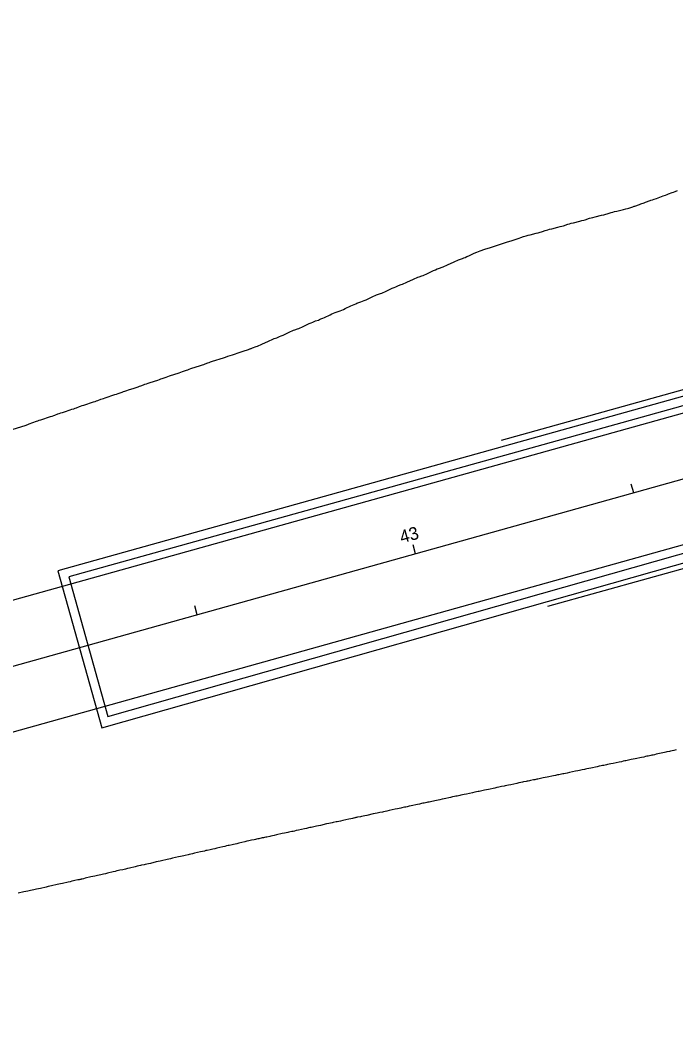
# Model space of a CAD drawing. Extents: x 1512289 to 1544686, y 552531 to 589211.
# Drawn here: x 1542830.9 to 1542975.5, y 587195.3 to 587418.5 of the extents above; entities that cross this region are included whole.
import ezdxf

# ---------------------------------------------------------------- set-up
doc = ezdxf.new("R2010")
doc.units = 0
for name, color, linetype in [('DR_X_Flood_Boundary', 7, 'Continuous'), ('DR_X_Underdrain', 7, 'Continuous'), ('DT_P_Graded_Shoulder', 7, 'Continuous'), ('GE_X_CL_20', 7, 'Continuous'), ('GK_Visualization', 7, 'Continuous'), ('PV_P_Text', 7, 'Continuous'), ('RW_P_Const_Limits', 7, 'Continuous')]:
    doc.layers.add(name, color=color, linetype=linetype)

msp = doc.modelspace()

# ---------------------------------------------------------------- linework, layer by layer
at = {"layer": 'DR_X_Flood_Boundary'}
for points in [[(1542829.08, 587328.21), (1542832.15, 587329.2), (1542832.7, 587329.38), (1542832.84, 587329.43), (1542834.45, 587330.03), (1542834.72, 587330.13), (1542835.05, 587330.24), (1542835.43, 587330.37), (1542835.87, 587330.52), (1542837.1, 587330.91), (1542837.53, 587331.06), (1542837.91, 587331.18), (1542838.24, 587331.3), (1542838.51, 587331.4), (1542839.17, 587331.64), (1542839.45, 587331.74), (1542839.78, 587331.86), (1542840.16, 587331.99), (1542840.59, 587332.13), (1542841.83, 587332.53), (1542842.26, 587332.67), (1542842.64, 587332.8), (1542842.97, 587332.91), (1542843.24, 587333.01), (1542843.9, 587333.26), (1542844.17, 587333.35), (1542844.5, 587333.47), (1542844.88, 587333.6), (1542845.32, 587333.74), (1542846.56, 587334.14), (1542846.99, 587334.28), (1542847.37, 587334.41), (1542847.7, 587334.53), (1542847.97, 587334.62), (1542848.63, 587334.87), (1542848.9, 587334.97), (1542849.23, 587335.08), (1542849.61, 587335.21), (1542850.05, 587335.35), (1542851.29, 587335.75), (1542851.72, 587335.9), (1542852.11, 587336.02), (1542852.43, 587336.14), (1542852.7, 587336.24), (1542853.35, 587336.48), (1542853.63, 587336.58), (1542853.95, 587336.69), (1542854.34, 587336.82), (1542854.77, 587336.96), (1542856.02, 587337.36), (1542856.45, 587337.51), (1542856.84, 587337.64), (1542857.16, 587337.75), (1542857.43, 587337.85), (1542858.08, 587338.09), (1542858.35, 587338.19), (1542858.68, 587338.3), (1542859.06, 587338.43), (1542859.5, 587338.57), (1542861.19, 587339.12), (1542861.57, 587339.25), (1542861.9, 587339.36), (1542862.16, 587339.46), (1542862.81, 587339.7), (1542863.08, 587339.79), (1542863.41, 587339.91), (1542863.79, 587340.04), (1542865.92, 587340.73), (1542866.3, 587340.86), (1542866.63, 587340.97), (1542866.9, 587341.07), (1542867.54, 587341.31), (1542867.81, 587341.4), (1542868.13, 587341.52), (1542868.52, 587341.64), (1542870.65, 587342.34), (1542871.03, 587342.47), (1542871.36, 587342.58), (1542871.63, 587342.68), (1542872.26, 587342.91), (1542872.53, 587343.01), (1542872.86, 587343.12), (1542873.24, 587343.25), (1542875.71, 587344.05), (1542876.13, 587344.19), (1542876.63, 587344.36), (1542877.65, 587344.7), (1542879.35, 587345.25), (1542880.06, 587345.48), (1542881.18, 587345.87), (1542881.35, 587345.93), (1542881.48, 587345.97), (1542881.56, 587346.01), (1542881.71, 587346.08), (1542881.79, 587346.11), (1542881.91, 587346.16), (1542882.08, 587346.22), (1542882.92, 587346.51), (1542883.18, 587346.6), (1542883.5, 587346.73), (1542883.87, 587346.9), (1542884.29, 587347.09), (1542885.49, 587347.66), (1542885.91, 587347.86), (1542886.28, 587348.02), (1542886.6, 587348.15), (1542886.86, 587348.25), (1542887.49, 587348.46), (1542887.75, 587348.56), (1542888.06, 587348.69), (1542888.43, 587348.85), (1542888.86, 587349.05), (1542890.06, 587349.61), (1542890.48, 587349.81), (1542890.85, 587349.97), (1542891.17, 587350.1), (1542891.43, 587350.2), (1542892.05, 587350.41), (1542892.32, 587350.51), (1542892.63, 587350.64), (1542893, 587350.8), (1542893.42, 587351), (1542894.62, 587351.56), (1542895.05, 587351.76), (1542895.42, 587351.92), (1542895.73, 587352.05), (1542896, 587352.15), (1542896.62, 587352.36), (1542896.88, 587352.46), (1542897.2, 587352.59), (1542897.57, 587352.75), (1542897.99, 587352.95), (1542899.19, 587353.51), (1542899.62, 587353.71), (1542899.98, 587353.87), (1542900.3, 587354), (1542900.56, 587354.1), (1542901.19, 587354.32), (1542901.45, 587354.41), (1542901.77, 587354.54), (1542902.14, 587354.71), (1542902.56, 587354.9), (1542903.76, 587355.47), (1542904.18, 587355.66), (1542904.55, 587355.82), (1542904.87, 587355.95), (1542905.13, 587356.05), (1542905.76, 587356.27), (1542906.02, 587356.37), (1542906.34, 587356.5), (1542906.71, 587356.66), (1542907.13, 587356.85), (1542908.33, 587357.42), (1542908.75, 587357.61), (1542909.12, 587357.77), (1542909.44, 587357.9), (1542909.7, 587358), (1542910.33, 587358.22), (1542910.59, 587358.32), (1542910.9, 587358.45), (1542911.27, 587358.61), (1542911.7, 587358.8), (1542912.9, 587359.37), (1542913.32, 587359.56), (1542913.69, 587359.72), (1542914, 587359.85), (1542914.27, 587359.95), (1542914.89, 587360.17), (1542915.16, 587360.27), (1542915.47, 587360.4), (1542915.84, 587360.56), (1542916.26, 587360.76), (1542917.46, 587361.32), (1542917.89, 587361.51), (1542918.26, 587361.67), (1542918.57, 587361.8), (1542918.83, 587361.9), (1542919.46, 587362.12), (1542919.73, 587362.22), (1542920.04, 587362.35), (1542920.41, 587362.51), (1542920.83, 587362.71), (1542922.03, 587363.27), (1542922.45, 587363.46), (1542922.81, 587363.62), (1542923.11, 587363.74), (1542923.35, 587363.83), (1542923.91, 587364.03), (1542924.15, 587364.12), (1542924.45, 587364.24), (1542924.81, 587364.4), (1542925.22, 587364.59), (1542926.42, 587365.15), (1542926.84, 587365.35), (1542927.21, 587365.51), (1542927.53, 587365.64), (1542927.79, 587365.74), (1542928.43, 587365.96), (1542928.69, 587366.06), (1542929.01, 587366.19), (1542929.38, 587366.35), (1542929.8, 587366.54), (1542930.99, 587367.1), (1542931.55, 587367.34), (1542932.34, 587367.63), (1542933.34, 587367.98), (1542934.57, 587368.38), (1542938.15, 587369.54), (1542939.35, 587369.93), (1542940.28, 587370.23), (1542940.92, 587370.44), (1542941.29, 587370.56), (1542941.89, 587370.77), (1542942.15, 587370.86), (1542942.48, 587370.95), (1542942.87, 587371.06), (1542943.34, 587371.18), (1542944.67, 587371.51), (1542945.13, 587371.63), (1542945.53, 587371.73), (1542945.85, 587371.83), (1542946.1, 587371.91), (1542946.67, 587372.11), (1542946.92, 587372.19), (1542947.24, 587372.28), (1542947.64, 587372.39), (1542948.12, 587372.51), (1542949.48, 587372.85), (1542949.95, 587372.97), (1542950.35, 587373.07), (1542950.67, 587373.16), (1542950.91, 587373.24), (1542951.45, 587373.43), (1542951.69, 587373.51), (1542952.01, 587373.6), (1542952.42, 587373.7), (1542952.9, 587373.83), (1542954.3, 587374.17), (1542954.78, 587374.29), (1542955.18, 587374.39), (1542955.49, 587374.48), (1542955.72, 587374.56), (1542956.23, 587374.73), (1542956.46, 587374.81), (1542956.78, 587374.9), (1542957.19, 587375), (1542957.68, 587375.12), (1542959.11, 587375.47), (1542959.61, 587375.59), (1542960.01, 587375.7), (1542960.32, 587375.78), (1542960.54, 587375.85), (1542961.01, 587376.02), (1542961.23, 587376.09), (1542961.55, 587376.18), (1542961.96, 587376.28), (1542962.46, 587376.4), (1542963.93, 587376.76), (1542964.43, 587376.88), (1542964.84, 587376.98), (1542965.15, 587377.07), (1542965.36, 587377.13), (1542965.79, 587377.28), (1542965.96, 587377.34), (1542966.12, 587377.4), (1542966.28, 587377.45), (1542966.44, 587377.51), (1542966.87, 587377.66), (1542967.05, 587377.72), (1542967.25, 587377.79), (1542967.49, 587377.88), (1542967.75, 587377.97), (1542968.5, 587378.24), (1542968.76, 587378.34), (1542969, 587378.42), (1542969.2, 587378.49), (1542969.37, 587378.55), (1542969.79, 587378.7), (1542970, 587378.77), (1542970.3, 587378.88), (1542970.71, 587379.02), (1542971.21, 587379.2), (1542972.68, 587379.73), (1542973.18, 587379.91), (1542973.58, 587380.06), (1542973.87, 587380.17), (1542974.07, 587380.25), (1542974.45, 587380.41), (1542974.64, 587380.48), (1542974.94, 587380.59), (1542975.34, 587380.74), (1542975.85, 587380.92)], [(1542975.54, 587257.52), (1542975.06, 587257.41), (1542974.65, 587257.32), (1542974.33, 587257.24), (1542974.07, 587257.19), (1542973.51, 587257.07), (1542973.27, 587257.02), (1542972.98, 587256.96), (1542972.65, 587256.89), (1542972.27, 587256.8), (1542971.18, 587256.55), (1542970.8, 587256.46), (1542970.47, 587256.39), (1542970.18, 587256.32), (1542969.94, 587256.27), (1542969.37, 587256.16), (1542969.12, 587256.1), (1542968.79, 587256.04), (1542968.39, 587255.95), (1542967.9, 587255.85), (1542966.52, 587255.56), (1542966.04, 587255.45), (1542965.63, 587255.37), (1542965.3, 587255.3), (1542965.05, 587255.25), (1542964.48, 587255.13), (1542964.22, 587255.08), (1542963.89, 587255.01), (1542963.49, 587254.92), (1542963.01, 587254.82), (1542961.63, 587254.53), (1542961.15, 587254.43), (1542960.74, 587254.35), (1542960.41, 587254.28), (1542960.16, 587254.22), (1542959.58, 587254.11), (1542959.33, 587254.05), (1542959, 587253.98), (1542958.59, 587253.9), (1542958.11, 587253.8), (1542956.74, 587253.51), (1542956.26, 587253.41), (1542955.86, 587253.32), (1542955.55, 587253.26), (1542955.31, 587253.21), (1542954.8, 587253.1), (1542954.56, 587253.05), (1542954.25, 587252.99), (1542953.86, 587252.91), (1542953.38, 587252.81), (1542952, 587252.52), (1542951.53, 587252.41), (1542951.12, 587252.33), (1542950.79, 587252.26), (1542950.53, 587252.21), (1542949.95, 587252.1), (1542949.69, 587252.05), (1542949.36, 587251.98), (1542948.96, 587251.89), (1542948.48, 587251.79), (1542947.11, 587251.5), (1542946.64, 587251.4), (1542946.23, 587251.32), (1542945.9, 587251.25), (1542945.64, 587251.2), (1542945.05, 587251.08), (1542944.83, 587251.04), (1542944.59, 587250.99), (1542944.35, 587250.94), (1542944.1, 587250.89), (1542943.43, 587250.75), (1542943.18, 587250.7), (1542942.94, 587250.65), (1542942.7, 587250.6), (1542942.48, 587250.55), (1542941.88, 587250.44), (1542941.62, 587250.38), (1542941.29, 587250.32), (1542940.88, 587250.23), (1542940.41, 587250.13), (1542939.05, 587249.83), (1542938.58, 587249.73), (1542938.18, 587249.64), (1542937.85, 587249.58), (1542937.59, 587249.52), (1542936.99, 587249.41), (1542936.73, 587249.35), (1542936.4, 587249.28), (1542936, 587249.2), (1542935.52, 587249.1), (1542934.16, 587248.8), (1542933.69, 587248.7), (1542933.29, 587248.61), (1542932.96, 587248.54), (1542932.7, 587248.49), (1542932.1, 587248.37), (1542931.84, 587248.32), (1542931.51, 587248.25), (1542931.11, 587248.17), (1542930.63, 587248.07), (1542929.28, 587247.77), (1542928.8, 587247.67), (1542928.4, 587247.58), (1542928.07, 587247.51), (1542927.81, 587247.46), (1542927.21, 587247.34), (1542926.95, 587247.29), (1542926.62, 587247.22), (1542926.22, 587247.14), (1542925.74, 587247.03), (1542924.39, 587246.74), (1542923.9, 587246.63), (1542923.44, 587246.53), (1542923.03, 587246.44), (1542922.65, 587246.36), (1542921.68, 587246.15), (1542921.34, 587246.08), (1542921.03, 587246.01), (1542920.76, 587245.95), (1542920.52, 587245.91), (1542919.93, 587245.79), (1542919.67, 587245.74), (1542919.34, 587245.67), (1542918.94, 587245.58), (1542918.46, 587245.48), (1542917.1, 587245.17), (1542916.63, 587245.07), (1542916.23, 587244.98), (1542915.9, 587244.91), (1542915.64, 587244.86), (1542915.04, 587244.74), (1542914.78, 587244.69), (1542914.45, 587244.62), (1542914.05, 587244.53), (1542913.58, 587244.43), (1542912.22, 587244.12), (1542911.75, 587244.02), (1542911.35, 587243.93), (1542911.02, 587243.86), (1542910.76, 587243.81), (1542910.15, 587243.69), (1542909.89, 587243.64), (1542909.56, 587243.57), (1542909.16, 587243.48), (1542908.69, 587243.38), (1542907.34, 587243.08), (1542906.87, 587242.97), (1542906.47, 587242.88), (1542906.14, 587242.81), (1542905.88, 587242.76), (1542905.27, 587242.64), (1542905.06, 587242.6), (1542904.89, 587242.57), (1542904.76, 587242.54), (1542904.67, 587242.53), (1542904.48, 587242.49), (1542904.35, 587242.46), (1542904.12, 587242.41), (1542903.78, 587242.34), (1542903.33, 587242.24), (1542901.99, 587241.94), (1542901.52, 587241.83), (1542901.12, 587241.74), (1542900.79, 587241.67), (1542900.52, 587241.62), (1542899.9, 587241.49), (1542899.64, 587241.43), (1542899.31, 587241.36), (1542898.91, 587241.28), (1542898.44, 587241.17), (1542897.11, 587240.87), (1542896.64, 587240.77), (1542896.24, 587240.68), (1542895.91, 587240.61), (1542895.64, 587240.55), (1542895.02, 587240.43), (1542894.75, 587240.37), (1542894.42, 587240.3), (1542894.02, 587240.21), (1542893.56, 587240.11), (1542892.23, 587239.81), (1542891.76, 587239.71), (1542891.36, 587239.62), (1542891.03, 587239.55), (1542890.76, 587239.49), (1542890.13, 587239.36), (1542889.86, 587239.31), (1542889.53, 587239.24), (1542889.13, 587239.15), (1542888.67, 587239.05), (1542887.35, 587238.75), (1542886.88, 587238.65), (1542886.48, 587238.56), (1542886.15, 587238.49), (1542885.88, 587238.43), (1542885.25, 587238.3), (1542885.01, 587238.25), (1542884.76, 587238.2), (1542884.5, 587238.14), (1542884.23, 587238.08), (1542883.51, 587237.92), (1542883.25, 587237.86), (1542882.99, 587237.81), (1542882.74, 587237.76), (1542882.49, 587237.71), (1542881.85, 587237.57), (1542881.58, 587237.52), (1542881.25, 587237.44), (1542880.85, 587237.35), (1542880.39, 587237.24), (1542879.09, 587236.93), (1542878.63, 587236.82), (1542878.23, 587236.73), (1542877.89, 587236.65), (1542877.62, 587236.59), (1542876.97, 587236.46), (1542876.7, 587236.4), (1542876.36, 587236.33), (1542875.97, 587236.24), (1542875.51, 587236.13), (1542874.21, 587235.82), (1542873.75, 587235.71), (1542873.36, 587235.61), (1542873.02, 587235.54), (1542872.74, 587235.48), (1542872.09, 587235.35), (1542871.81, 587235.29), (1542871.47, 587235.21), (1542871.08, 587235.12), (1542870.63, 587235.01), (1542869.33, 587234.71), (1542868.88, 587234.6), (1542868.48, 587234.51), (1542868.15, 587234.43), (1542867.87, 587234.37), (1542867.2, 587234.24), (1542866.92, 587234.18), (1542866.59, 587234.1), (1542866.19, 587234.01), (1542865.74, 587233.9), (1542864.46, 587233.6), (1542864.01, 587233.49), (1542863.61, 587233.4), (1542863.27, 587233.32), (1542862.99, 587233.26), (1542862.32, 587233.13), (1542862.04, 587233.07), (1542861.7, 587232.99), (1542861.31, 587232.9), (1542860.86, 587232.79), (1542859.58, 587232.49), (1542859.14, 587232.38), (1542858.76, 587232.29), (1542858.44, 587232.22), (1542858.19, 587232.17), (1542857.6, 587232.05), (1542857.35, 587232), (1542857.03, 587231.93), (1542856.65, 587231.84), (1542856.21, 587231.73), (1542854.94, 587231.43), (1542854.49, 587231.32), (1542854.1, 587231.23), (1542853.76, 587231.16), (1542853.48, 587231.09), (1542852.79, 587230.95), (1542852.51, 587230.89), (1542852.17, 587230.81), (1542851.78, 587230.72), (1542851.33, 587230.61), (1542850.07, 587230.31), (1542849.63, 587230.2), (1542849.23, 587230.11), (1542848.89, 587230.03), (1542848.61, 587229.97), (1542847.91, 587229.82), (1542847.63, 587229.76), (1542847.29, 587229.69), (1542846.9, 587229.59), (1542846.45, 587229.49), (1542845.2, 587229.19), (1542844.79, 587229.09), (1542844.48, 587229.02), (1542844.29, 587228.97), (1542844.22, 587228.95), (1542844.16, 587228.94), (1542844.11, 587228.93), (1542843.99, 587228.9), (1542843.82, 587228.87), (1542843.59, 587228.82), (1542842.89, 587228.67), (1542842.6, 587228.61), (1542842.26, 587228.53), (1542841.87, 587228.44), (1542841.43, 587228.34), (1542840.18, 587228.06), (1542839.73, 587227.96), (1542839.34, 587227.87), (1542839, 587227.79), (1542838.71, 587227.73), (1542838.02, 587227.58), (1542837.73, 587227.52), (1542837.39, 587227.45), (1542837, 587227.36), (1542836.55, 587227.26), (1542835.3, 587226.97), (1542834.85, 587226.87), (1542834.46, 587226.78), (1542834.12, 587226.71), (1542833.84, 587226.65), (1542833.14, 587226.5), (1542832.85, 587226.44), (1542832.51, 587226.36), (1542832.12, 587226.28), (1542831.68, 587226.17), (1542830.42, 587225.89)]]:
    msp.add_lwpolyline(points, dxfattribs=at)
at = {"layer": 'DR_X_Underdrain'}
for p, q in [((1543116.66, 587370.84), (1541208.48, 586837.66)), ((1543114.38, 587341.13), (1541216.02, 586810.7))]:
    msp.add_line(p, q, dxfattribs=at)
at = {"layer": 'DT_P_Graded_Shoulder'}
for p, q in [((1542937, 587325.83), (1543130.63, 587379.93)), ((1542947.23, 587289.23), (1543123.44, 587338.47))]:
    msp.add_line(p, q, dxfattribs=at)
at = {"layer": 'GE_X_CL_20'}
for p, q in [((1541212.25, 586824.18), (1543339.29, 587418.51)), ((1542966.2, 587314.26), (1542965.66, 587316.18)), ((1542918.04, 587300.8), (1542917.5, 587302.73)), ((1542869.88, 587287.35), (1542869.35, 587289.27))]:
    msp.add_line(p, q, dxfattribs=at)
at = {"layer": 'GK_Visualization'}
msp.add_line((1541212.25, 586824.18), (1543339.29, 587418.51), dxfattribs=at)
at = {"layer": 'PV_P_Text'}
msp.add_lwpolyline([(1543066.67, 587326.26), (1543058.35, 587356.05), (1542841.6, 587295.67), (1542850.21, 587264.86)], close=True, dxfattribs=at)
at = {"layer": 'RW_P_Const_Limits'}
msp.add_lwpolyline([(1542981.95, 587336.85), (1542839.14, 587297.06), (1542848.82, 587262.39), (1542980.12, 587299.63)], dxfattribs=at)

# ---------------------------------------------------------------- texts
at = {"layer": 'GE_X_CL_20'}
msp.add_text('43', height=2.8, rotation=15.6111, dxfattribs=at).set_placement((1542915.01, 587303.07))

doc.saveas('drawing.dxf')
